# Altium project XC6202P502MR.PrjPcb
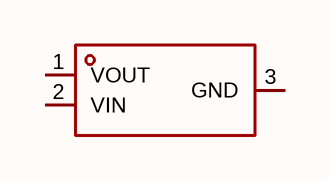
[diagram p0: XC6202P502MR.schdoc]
1 sheet, 1 parts. Net scope: global (net labels, ports and power ports of the same name join across sheets).

## Sheet XC6202P502MR.schdoc
size 127 x 101 mm

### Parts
U?  xc6202p502mr  [SOT-23-3_L2.9-W1.6-P1.90-LS2.8-BR]  (value not drawn)

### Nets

Not connected (* = marked no-connect by the designer): U? 1(VOUT) 2(VIN) 3(GND)

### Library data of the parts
U? = xc6202p502mr: 输出极性:正极;工作电压:15V;输出电压:5V;输出电流:150mA;电源纹波抑制比(PSRR):-;输出类型:固定;; Manufacturer: TECH PUBLIC(台舟); AddInBom: yes; ModelId: 89cb27a44ab2466697082bb9fd73a7d0; ModelName: SOT-23-3L_L2.9-W1.6-H1.1-LS2.8-P0.95; ModelTransform: 114.173,110.236,0,90,0,0,0,0,0; Output Configuration: 正极; Voltage - Supply: 15V; Output Voltage: 5V; Output Current: 150mA; Voltage Dropout: 180mV@(100mA); standby current: 2uA; Output Type: 固定; Number of Outputs: 1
